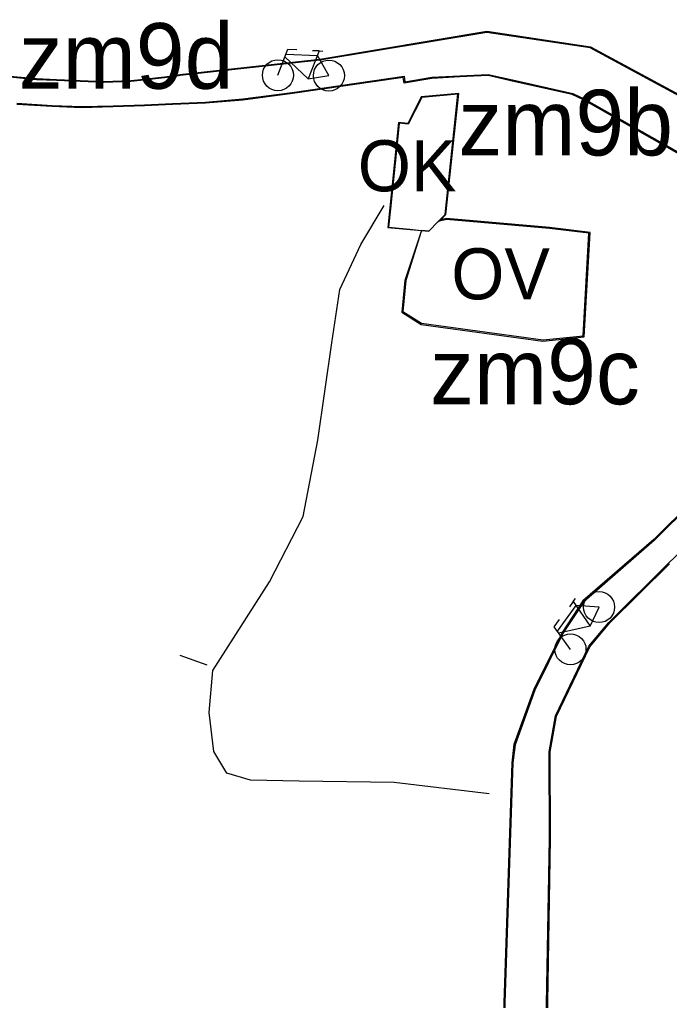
# Model space of a CAD drawing. Extents: x -555070 to -553076, y -1186731 to -1182766.
# Drawn here: x -554743.6 to -554565.4, y -1184757.3 to -1184488.3 of the extents above; entities that cross this region are included whole.
import ezdxf

# ---------------------------------------------------------------- set-up
doc = ezdxf.new("R2010")
doc.units = 0
for name, color, linetype in [('CYKLISTI_stav', 7, 'Continuous'), ('HRANICE_ZMENY_DO_KOO', 7, 'Continuous'), ('Level 10', 7, 'Continuous'), ('Level 59', 7, 'Continuous'), ('Level 6', 7, 'Continuous'), ('OBRYS_PLOCH', 7, 'Continuous'), ('stav_DS', 7, 'Continuous'), ('stav_OK', 7, 'Continuous'), ('stav_OV', 7, 'Continuous')]:
    doc.layers.add(name, color=color, linetype=linetype)

msp = doc.modelspace()

# ---------------------------------------------------------------- linework, layer by layer
at = {"layer": 'CYKLISTI_stav'}
for p, q in [((-554672.76, -1184503.57), (-554670.04, -1184496.43)), ((-554670.04, -1184496.43), (-554667.6, -1184496.5)), ((-554661.43, -1184496.92), (-554664.45, -1184504.55)), ((-554661.43, -1184496.92), (-554663.25, -1184496.88)), ((-554661.43, -1184496.92), (-554660.43, -1184496.97)), ((-554664.45, -1184504.55), (-554670.83, -1184498.5)), ((-554670.58, -1184497.83), (-554661.94, -1184498.2)), ((-554658.77, -1184503.68), (-554661.94, -1184498.2)), ((-554664.45, -1184504.55), (-554658.77, -1184503.68)), ((-554591.78, -1184647.89), (-554592.82, -1184649.38)), ((-554591.78, -1184647.89), (-554591.19, -1184647.09)), ((-554591.78, -1184647.89), (-554587.1, -1184654.63)), ((-554596.09, -1184656.01), (-554591, -1184649.02)), ((-554584.68, -1184649.42), (-554591, -1184649.02)), ((-554587.1, -1184654.63), (-554584.68, -1184649.42)), ((-554596.96, -1184654.79), (-554595.54, -1184652.8)), ((-554592.52, -1184661.01), (-554596.96, -1184654.79)), ((-554587.1, -1184654.63), (-554595.67, -1184656.59))]:
    msp.add_line(p, q, dxfattribs=at)
for centre in [(-554672.76, -1184503.57), (-554658.77, -1184503.68), (-554584.68, -1184649.42), (-554592.52, -1184661.01)]:
    msp.add_circle(centre, 4.25, dxfattribs=at)
at = {"layer": 'HRANICE_ZMENY_DO_KOO'}
for p, q in [((-554661.26, -1184499.14), (-554615.47, -1184491.53)), ((-554615.47, -1184491.53), (-554587.06, -1184495.79)), ((-554587.06, -1184495.79), (-554557.31, -1184511.89)), ((-554699.62, -1184503.35), (-554661.26, -1184499.14)), ((-554746.33, -1184503.84), (-554738.94, -1184504.5)), ((-554738.94, -1184504.5), (-554733.49, -1184504.73)), ((-554733.49, -1184504.73), (-554720.52, -1184505.29)), ((-554720.52, -1184505.29), (-554713.09, -1184505.04)), ((-554713.09, -1184505.04), (-554709.53, -1184504.68)), ((-554709.53, -1184504.68), (-554701.49, -1184503.74)), ((-554701.49, -1184503.74), (-554699.62, -1184503.35)), ((-554638.42, -1184504.16), (-554668.78, -1184508.59)), ((-554638.16, -1184505.76), (-554638.42, -1184504.16)), ((-554630.5, -1184504.45), (-554638.16, -1184505.76)), ((-554622.86, -1184504.06), (-554630.5, -1184504.45)), ((-554615.13, -1184503.67), (-554622.86, -1184504.06)), ((-554607.65, -1184505.36), (-554615.13, -1184503.67)), ((-554592.02, -1184508.91), (-554607.65, -1184505.36)), ((-554682.38, -1184510.38), (-554692.63, -1184511.28)), ((-554668.78, -1184508.59), (-554682.38, -1184510.38)), ((-554588.94, -1184510.3), (-554592.02, -1184508.91)), ((-554562.72, -1184525.2), (-554588.94, -1184510.3)), ((-554734.67, -1184512.17), (-554744.37, -1184511.58)), ((-554726.63, -1184512.48), (-554734.67, -1184512.17)), ((-554717.89, -1184512.29), (-554726.63, -1184512.48)), ((-554709.31, -1184511.96), (-554717.89, -1184512.29)), ((-554701.66, -1184511.61), (-554709.31, -1184511.96)), ((-554692.63, -1184511.28), (-554701.66, -1184511.61)), ((-554548.54, -1184609.85), (-554569.7, -1184630.88)), ((-554569.7, -1184630.88), (-554589.1, -1184647.73)), ((-554581.82, -1184653.86), (-554565.38, -1184637.51)), ((-554589.1, -1184647.73), (-554594.79, -1184656.35)), ((-554587.23, -1184660.31), (-554581.82, -1184653.86)), ((-554594.79, -1184656.35), (-554602.54, -1184672.05)), ((-554596.33, -1184679.33), (-554587.23, -1184660.31)), ((-554602.54, -1184672.05), (-554608.02, -1184687.08)), ((-554598.08, -1184689.13), (-554596.33, -1184679.33)), ((-554608.02, -1184687.08), (-554608.62, -1184692.09)), ((-554597.99, -1184712.84), (-554598.08, -1184689.13)), ((-554608.62, -1184692.09), (-554612.83, -1184818.2)), ((-554599.64, -1184809.83), (-554597.99, -1184712.84))]:
    msp.add_line(p, q, dxfattribs=at)
for points in [[(-554626.67, -1184541.79), (-554623.18, -1184508.57), (-554633.46, -1184509.51), (-554637.14, -1184516.79), (-554639.65, -1184516.52), (-554642.65, -1184545.37), (-554633.35, -1184546.14)], [(-554633.35, -1184546.14), (-554637.95, -1184559.83), (-554638.8, -1184568.52), (-554633.48, -1184571.9), (-554600.06, -1184576.46), (-554588.76, -1184575.34), (-554587.14, -1184546.67), (-554598.28, -1184545.29), (-554626.51, -1184542.88), (-554628.24, -1184543.36)], [(-554633.35, -1184546.14), (-554631.37, -1184546.32), (-554628.76, -1184543.68), (-554628.11, -1184543.26), (-554626.67, -1184541.79)]]:
    msp.add_lwpolyline(points, dxfattribs=at)
at = {"layer": 'Level 6'}
msp.add_line((-554692.16, -1184665.31), (-554699.53, -1184662.69), dxfattribs=at)
msp.add_lwpolyline([(-554614.83, -1184700.62), (-554640.88, -1184697.53), (-554666.93, -1184697.11), (-554680.31, -1184696.9), (-554686.76, -1184694.96), (-554690.32, -1184689.01), (-554691.58, -1184678.34), (-554690.64, -1184666.83), (-554675.07, -1184642.45), (-554665.86, -1184624.55), (-554661.85, -1184603.63), (-554657.93, -1184577), (-554655.76, -1184562.3), (-554650.04, -1184550.02), (-554643.65, -1184539.29)], dxfattribs=at)
at = {"layer": 'OBRYS_PLOCH'}
for p, q in [((-554615.47, -1184491.83), (-554661.22, -1184499.44)), ((-554615.47, -1184491.83), (-554661.22, -1184499.44)), ((-554587.16, -1184496.08), (-554615.47, -1184491.83)), ((-554587.16, -1184496.08), (-554615.47, -1184491.83)), ((-554557.42, -1184512.17), (-554587.16, -1184496.08)), ((-554557.42, -1184512.17), (-554587.16, -1184496.08)), ((-554661.22, -1184499.44), (-554699.57, -1184503.65)), ((-554661.22, -1184499.44), (-554699.57, -1184503.65)), ((-554738.96, -1184504.8), (-554746.28, -1184504.15)), ((-554738.96, -1184504.8), (-554746.28, -1184504.15)), ((-554733.5, -1184505.03), (-554738.96, -1184504.8)), ((-554733.5, -1184505.03), (-554738.96, -1184504.8)), ((-554720.52, -1184505.59), (-554733.5, -1184505.03)), ((-554720.52, -1184505.59), (-554733.5, -1184505.03)), ((-554713.07, -1184505.34), (-554720.52, -1184505.59)), ((-554713.07, -1184505.34), (-554720.52, -1184505.59)), ((-554709.5, -1184504.98), (-554713.07, -1184505.34)), ((-554709.5, -1184504.98), (-554713.07, -1184505.34)), ((-554701.44, -1184504.04), (-554709.5, -1184504.98)), ((-554701.44, -1184504.04), (-554709.5, -1184504.98)), ((-554699.57, -1184503.65), (-554701.44, -1184504.04)), ((-554699.57, -1184503.65), (-554701.44, -1184504.04)), ((-554668.82, -1184508.29), (-554638.17, -1184503.82)), ((-554668.82, -1184508.29), (-554638.17, -1184503.82)), ((-554638.17, -1184503.82), (-554637.91, -1184505.41)), ((-554638.17, -1184503.82), (-554637.91, -1184505.41)), ((-554637.91, -1184505.41), (-554630.53, -1184504.15)), ((-554637.91, -1184505.41), (-554630.53, -1184504.15)), ((-554630.53, -1184504.15), (-554622.88, -1184503.76)), ((-554630.53, -1184504.15), (-554622.88, -1184503.76)), ((-554622.88, -1184503.76), (-554615.1, -1184503.37)), ((-554622.88, -1184503.76), (-554615.1, -1184503.37)), ((-554615.1, -1184503.37), (-554607.58, -1184505.07)), ((-554615.1, -1184503.37), (-554607.58, -1184505.07)), ((-554607.58, -1184505.07), (-554591.92, -1184508.62)), ((-554607.58, -1184505.07), (-554591.92, -1184508.62)), ((-554682.41, -1184510.08), (-554668.82, -1184508.29)), ((-554682.41, -1184510.08), (-554668.82, -1184508.29)), ((-554701.67, -1184511.31), (-554692.65, -1184510.98)), ((-554701.67, -1184511.31), (-554692.65, -1184510.98)), ((-554692.65, -1184510.98), (-554682.41, -1184510.08)), ((-554692.65, -1184510.98), (-554682.41, -1184510.08)), ((-554591.92, -1184508.62), (-554588.8, -1184510.03)), ((-554591.92, -1184508.62), (-554588.8, -1184510.03)), ((-554588.8, -1184510.03), (-554562.63, -1184524.9)), ((-554588.8, -1184510.03), (-554562.63, -1184524.9)), ((-554744.35, -1184511.28), (-554734.66, -1184511.87)), ((-554744.35, -1184511.28), (-554734.66, -1184511.87)), ((-554734.66, -1184511.87), (-554726.63, -1184512.18)), ((-554734.66, -1184511.87), (-554726.63, -1184512.18)), ((-554726.63, -1184512.18), (-554717.9, -1184511.99)), ((-554726.63, -1184512.18), (-554717.9, -1184511.99)), ((-554717.9, -1184511.99), (-554709.32, -1184511.66)), ((-554717.9, -1184511.99), (-554709.32, -1184511.66)), ((-554709.32, -1184511.66), (-554701.67, -1184511.31)), ((-554709.32, -1184511.66), (-554701.67, -1184511.31)), ((-554628.76, -1184543.68), (-554631.37, -1184546.32)), ((-554633.44, -1184546.43), (-554637.65, -1184559.89)), ((-554633.35, -1184546.14), (-554633.44, -1184546.43)), ((-554631.37, -1184546.32), (-554633.35, -1184546.14)), ((-554637.65, -1184559.89), (-554638.48, -1184568.37)), ((-554638.48, -1184568.37), (-554633.37, -1184571.61)), ((-554633.37, -1184571.61), (-554600.05, -1184576.16)), ((-554600.05, -1184576.16), (-554589.05, -1184575.07)), ((-554565.59, -1184637.29), (-554524.68, -1184598.92)), ((-554565.59, -1184637.29), (-554524.68, -1184598.92)), ((-554548.33, -1184610.06), (-554569.5, -1184631.1)), ((-554548.33, -1184610.06), (-554569.5, -1184631.1)), ((-554569.5, -1184631.1), (-554588.87, -1184647.93)), ((-554569.5, -1184631.1), (-554588.87, -1184647.93)), ((-554582.04, -1184653.66), (-554565.59, -1184637.29)), ((-554582.04, -1184653.66), (-554565.59, -1184637.29)), ((-554588.87, -1184647.93), (-554594.53, -1184656.5)), ((-554588.87, -1184647.93), (-554594.53, -1184656.5)), ((-554587.48, -1184660.15), (-554582.04, -1184653.66)), ((-554587.48, -1184660.15), (-554582.04, -1184653.66)), ((-554594.53, -1184656.5), (-554602.26, -1184672.17)), ((-554594.53, -1184656.5), (-554602.26, -1184672.17)), ((-554596.62, -1184679.24), (-554587.48, -1184660.15)), ((-554596.62, -1184679.24), (-554587.48, -1184660.15)), ((-554602.26, -1184672.17), (-554607.73, -1184687.15)), ((-554602.26, -1184672.17), (-554607.73, -1184687.15)), ((-554598.38, -1184689.1), (-554596.62, -1184679.24)), ((-554598.38, -1184689.1), (-554596.62, -1184679.24)), ((-554607.73, -1184687.15), (-554608.32, -1184692.11)), ((-554607.73, -1184687.15), (-554608.32, -1184692.11)), ((-554598.29, -1184712.84), (-554598.38, -1184689.1)), ((-554598.29, -1184712.84), (-554598.38, -1184689.1)), ((-554608.32, -1184692.11), (-554612.53, -1184818.21)), ((-554608.32, -1184692.11), (-554612.53, -1184818.21)), ((-554599.64, -1184792.05), (-554598.29, -1184712.84)), ((-554599.64, -1184792.05), (-554598.29, -1184712.84))]:
    msp.add_line(p, q, dxfattribs=at)
msp.add_lwpolyline([(-554633.35, -1184546.14), (-554631.37, -1184546.32), (-554628.76, -1184543.68), (-554626.87, -1184541.77), (-554623.41, -1184508.79), (-554633.33, -1184509.7), (-554637.02, -1184517), (-554639.47, -1184516.74), (-554640.14, -1184523.18), (-554641.91, -1184540.17), (-554642.43, -1184545.2), (-554636.54, -1184545.76)], close=True, dxfattribs=at)
for points in [[(-554598.31, -1184545.59), (-554626.5, -1184543.18), (-554628.76, -1184543.68)], [(-554589.05, -1184575.07), (-554587.46, -1184546.93), (-554598.31, -1184545.59)]]:
    msp.add_lwpolyline(points, dxfattribs=at)
at = {"layer": 'stav_DS'}
for p, q in [((-554615.47, -1184491.83), (-554661.22, -1184499.44)), ((-554587.16, -1184496.08), (-554615.47, -1184491.83)), ((-554557.42, -1184512.17), (-554587.16, -1184496.08)), ((-554661.22, -1184499.44), (-554699.57, -1184503.65)), ((-554738.96, -1184504.8), (-554746.28, -1184504.15)), ((-554733.5, -1184505.03), (-554738.96, -1184504.8)), ((-554720.52, -1184505.59), (-554733.5, -1184505.03)), ((-554713.07, -1184505.34), (-554720.52, -1184505.59)), ((-554709.5, -1184504.98), (-554713.07, -1184505.34)), ((-554701.44, -1184504.04), (-554709.5, -1184504.98)), ((-554699.57, -1184503.65), (-554701.44, -1184504.04)), ((-554668.82, -1184508.29), (-554638.17, -1184503.82)), ((-554638.17, -1184503.82), (-554637.91, -1184505.41)), ((-554637.91, -1184505.41), (-554630.53, -1184504.15)), ((-554630.53, -1184504.15), (-554622.88, -1184503.76)), ((-554622.88, -1184503.76), (-554615.1, -1184503.37)), ((-554615.1, -1184503.37), (-554607.58, -1184505.07)), ((-554607.58, -1184505.07), (-554591.92, -1184508.62)), ((-554682.41, -1184510.08), (-554668.82, -1184508.29)), ((-554701.67, -1184511.31), (-554692.65, -1184510.98)), ((-554692.65, -1184510.98), (-554682.41, -1184510.08)), ((-554591.92, -1184508.62), (-554588.8, -1184510.03)), ((-554588.8, -1184510.03), (-554562.63, -1184524.9)), ((-554744.35, -1184511.28), (-554734.66, -1184511.87)), ((-554734.66, -1184511.87), (-554726.63, -1184512.18)), ((-554726.63, -1184512.18), (-554717.9, -1184511.99)), ((-554717.9, -1184511.99), (-554709.32, -1184511.66)), ((-554709.32, -1184511.66), (-554701.67, -1184511.31)), ((-554565.59, -1184637.29), (-554524.68, -1184598.92)), ((-554548.33, -1184610.06), (-554569.5, -1184631.1)), ((-554569.5, -1184631.1), (-554588.87, -1184647.93)), ((-554582.04, -1184653.66), (-554565.59, -1184637.29)), ((-554588.87, -1184647.93), (-554594.53, -1184656.5)), ((-554587.48, -1184660.15), (-554582.04, -1184653.66)), ((-554594.53, -1184656.5), (-554602.26, -1184672.17)), ((-554596.62, -1184679.24), (-554587.48, -1184660.15)), ((-554602.26, -1184672.17), (-554607.73, -1184687.15)), ((-554598.38, -1184689.1), (-554596.62, -1184679.24)), ((-554607.73, -1184687.15), (-554608.32, -1184692.11)), ((-554598.29, -1184712.84), (-554598.38, -1184689.1)), ((-554608.32, -1184692.11), (-554612.53, -1184818.21)), ((-554599.64, -1184792.05), (-554598.29, -1184712.84))]:
    msp.add_line(p, q, dxfattribs=at)
at = {"layer": 'stav_OK'}
msp.add_lwpolyline([(-554633.35, -1184546.14), (-554631.37, -1184546.32), (-554628.76, -1184543.68), (-554626.87, -1184541.77), (-554623.41, -1184508.79), (-554633.33, -1184509.7), (-554637.02, -1184517), (-554639.47, -1184516.74), (-554640.14, -1184523.18), (-554641.91, -1184540.17), (-554642.43, -1184545.2), (-554636.54, -1184545.76)], close=True, dxfattribs=at)
at = {"layer": 'stav_OV'}
for p, q in [((-554628.76, -1184543.68), (-554631.37, -1184546.32)), ((-554633.44, -1184546.43), (-554637.65, -1184559.89)), ((-554633.35, -1184546.14), (-554633.44, -1184546.43)), ((-554631.37, -1184546.32), (-554633.35, -1184546.14)), ((-554637.65, -1184559.89), (-554638.48, -1184568.37)), ((-554638.48, -1184568.37), (-554633.37, -1184571.61)), ((-554633.37, -1184571.61), (-554600.05, -1184576.16)), ((-554600.05, -1184576.16), (-554589.05, -1184575.07))]:
    msp.add_line(p, q, dxfattribs=at)
for points in [[(-554598.31, -1184545.59), (-554626.5, -1184543.18), (-554628.76, -1184543.68)], [(-554589.05, -1184575.07), (-554587.46, -1184546.93), (-554598.31, -1184545.59)]]:
    msp.add_lwpolyline(points, dxfattribs=at)

# ---------------------------------------------------------------- texts
at = {"layer": 'Level 10'}
for s, p in [('zm9d', (-554743.8, -1184507.29)), ('zm9b', (-554623.26, -1184525.58)), ('zm9c', (-554631.01, -1184593.81))]:
    msp.add_text(s, height=18, dxfattribs=at).set_placement(p)
at = {"layer": 'Level 59'}
for s, p in [('OK', (-554650.84, -1184535.41)), ('OV', (-554625.21, -1184565.03))]:
    msp.add_text(s, height=14, dxfattribs=at).set_placement(p)

doc.saveas('drawing.dxf')
